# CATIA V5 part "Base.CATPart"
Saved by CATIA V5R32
Part number: Base
Bounding box of the stored display mesh (mm): x -23.876 to 23.876, y 0 to 88.9, z 0 to 54.102
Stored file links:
  D:\PROJECTS\Project 2022\CATIA V5 6R 2022\Resources\Input file\c14_catia_v5_6r2022_inp\c14_catia_v5_6r2022_inp\Base.CATPart
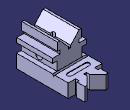
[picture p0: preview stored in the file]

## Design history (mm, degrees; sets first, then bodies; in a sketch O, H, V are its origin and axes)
Body1 (main body)
  Sketch1 on xy-plane, origin (0, 0, 0), H (1, 0, 0), V (0, 1, 0)
    line L1 (-23.876, 0) -> (23.876, 0)
    point P1 (-23.876, 0)
    point P2 (23.876, 0)
    construction line L2 (-23.876, 50.8) -> (23.876, 50.8)
    point P3 (-23.876, 50.8)
    point P4 (23.876, 50.8)
    line L3 (23.876, 0) -> (23.876, 72.898)
    point P5 (23.876, 72.898)
    line L4 (23.876, 72.898) -> (13.462, 72.898)
    point P6 (13.462, 72.898)
    line L5 (13.462, 72.898) -> (13.462, 77.724)
    point P7 (13.462, 77.724)
    line L6 (13.462, 77.724) -> (16.51, 77.724)
    point P8 (16.51, 77.724)
    line L7 (16.51, 77.724) -> (16.51, 88.9)
    point P9 (16.51, 88.9)
    line L8 (16.51, 88.9) -> (13.462, 88.9)
    point P10 (13.462, 88.9)
    line L9 (13.462, 88.9) -> (1.778, 77.724)
    point P11 (1.778, 77.724)
    line L10 (1.778, 77.724) -> (1.778, 72.898)
    point P12 (1.778, 72.898)
    line L11 (1.778, 72.898) -> (0, 72.898)
    point P13 (0, 72.898)
    point P14 (0, 72.898)
    point P15 (-1.778, 72.898)
    line L12 (-1.778, 72.898) -> (0, 72.898)
    point P16 (-1.778, 77.724)
    line L13 (-1.778, 77.724) -> (-1.778, 72.898)
    point P17 (-13.462, 88.9)
    line L14 (-13.462, 88.9) -> (-1.778, 77.724)
    point P18 (-16.51, 88.9)
    line L15 (-16.51, 88.9) -> (-13.462, 88.9)
    point P19 (-16.51, 77.724)
    line L16 (-16.51, 77.724) -> (-16.51, 88.9)
    point P20 (-13.462, 77.724)
    line L17 (-13.462, 77.724) -> (-16.51, 77.724)
    point P21 (-13.462, 72.898)
    line L18 (-13.462, 72.898) -> (-13.462, 77.724)
    point P22 (-23.876, 72.898)
    line L19 (-23.876, 72.898) -> (-13.462, 72.898)
    point P23 (-23.876, 50.8)
    point P24 (23.876, 50.8)
    construction line L20 (23.876, 50.8) -> (-23.876, 50.8)
    point P25 (-23.876, 0)
    line L21 (-23.876, 0) -> (-23.876, 72.898)
    length L1 = 47.752
    distance P2 V = 23.876
    distance L2 L1 = 50.8
    distance P5 L2 = 22.098
    distance L7 P1 = 40.386
    distance L5 P1 = 37.338
    distance L2 P7 = 26.924
    distance P9 L2 = 38.1
    distance P10 L3 = 10.414
    distance L10 L3 = 22.098
    distance L11 L2 = 22.098
    distance P11 L2 = 26.924
    horizontal: L1 H, L2 H, L4 H, L6 H, L8 H, L11 H
    coincidence: H L1, P13 V, P13 P14
    vertical: L3 V, L5 V, L7 V, L10 V
    symmetry: P13 P14 V, P12 P15 V, L11 L12 V, P11 P16 V, L10 L13 V, P10 P17 V, L9 L14 V, P9 P18 V, L8 L15 V, P8 P19 V, L7 L16 V, P7 P20 V, L6 L17 V, P6 P21 V, L5 L18 V, P5 P22 V, L4 L19 V, P4 P23 V, P3 P24 V, L2 L20 V, P2 P25 V, L3 L21 V
  Pad1: profile Sketch1, direction (0, 0, 1), length 19.05
  Sketch2 on face of Pad1, origin (23.876, 0, 0), H (0, 1, 0), V (0, 0, 1)
    point P1 (50.8, 19.05)
    line L1 (50.8, 19.05) -> (52.324, 16.4104)
    line L2 (52.324, 16.4104) -> (53.848, 19.05)
    line L3 (53.848, 19.05) -> (50.8, 19.05)
    reference projected line E1 (72.898, 19.05) -> (0, 19.05) from edge of Pad1
    length L2 = 3.048
    length L1 = 3.048
    distance P1 V = 50.8
    angle L1 L2 = 60
    horizontal: L3 H
    coincidence: L3 E1
  Pocket1: profile Sketch2, direction (-1, 0, 0), through (limit type 6)
  Sketch3 on face of Pad1, origin (0, 0, 0), H (1, 0, 0), V (0, 0, 1)
    line L1 (17.526, 19.05) -> (17.526, 31.75)
    point P1 (17.526, 19.05)
    point P2 (17.526, 31.75)
    line L2 (17.526, 31.75) -> (23.876, 31.75)
    point P3 (23.876, 31.75)
    line L3 (23.876, 31.75) -> (23.876, 38.1)
    point P4 (23.876, 38.1)
    line L4 (23.876, 38.1) -> (13.462, 38.1)
    point P5 (13.462, 38.1)
    line L5 (13.462, 38.1) -> (13.462, 42.926)
    point P6 (13.462, 42.926)
    line L6 (13.462, 42.926) -> (16.637, 42.926)
    point P7 (16.637, 42.926)
    line L7 (16.637, 42.926) -> (16.637, 54.102)
    point P8 (16.637, 54.102)
    reference projected line E1 (23.876, 19.05) -> (-23.876, 19.05) from edge of Pad1
    reference projected line E2 (23.876, 0) -> (23.876, 19.05) from edge of Pad1
    reference projected line E3 (-23.876, 19.05) -> (-23.876, 0) from edge of Pad1
    line L8 (16.637, 54.102) -> (13.462, 54.102)
    point P9 (13.462, 54.102)
    point P10 (1.651, 41.402)
    line L9 (1.651, 41.402) -> (1.651, 38.1)
    point P11 (1.651, 38.1)
    line L10 (1.651, 38.1) -> (0, 38.1)
    point P12 (0, 38.1)
    line L11 (1.651, 41.402) -> (13.462, 54.102)
    point P13 (-13.462, 54.102)
    point P14 (-1.651, 41.402)
    line L12 (-1.651, 41.402) -> (-13.462, 54.102)
    point P15 (0, 38.1)
    point P16 (-1.651, 38.1)
    line L13 (-1.651, 38.1) -> (0, 38.1)
    line L14 (-1.651, 41.402) -> (-1.651, 38.1)
    point P17 (-16.637, 54.102)
    line L15 (-16.637, 54.102) -> (-13.462, 54.102)
    point P18 (-16.637, 42.926)
    line L16 (-16.637, 42.926) -> (-16.637, 54.102)
    point P19 (-13.462, 42.926)
    line L17 (-13.462, 42.926) -> (-16.637, 42.926)
    point P20 (-13.462, 38.1)
    line L18 (-13.462, 38.1) -> (-13.462, 42.926)
    point P21 (-23.876, 38.1)
    line L19 (-23.876, 38.1) -> (-13.462, 38.1)
    point P22 (-23.876, 31.75)
    line L20 (-23.876, 31.75) -> (-23.876, 38.1)
    point P23 (-17.526, 31.75)
    line L21 (-17.526, 31.75) -> (-23.876, 31.75)
    point P24 (-17.526, 19.05)
    line L22 (-17.526, 19.05) -> (-17.526, 31.75)
    line L23 (-17.526, 19.05) -> (17.526, 19.05)
    distance V L1 = 17.526
    distance L2 H = 31.75
    distance L4 H = 38.1
    distance L6 H = 42.926
    distance L7 V = 16.637
    distance L5 E3 = 37.338
    distance V P9 = 13.462
    distance L8 H = 54.102
    distance L9 V = 1.651
    length L9 = 3.302
    vertical: L1 V, L3 V, L5 V, L7 V, L9 V
    horizontal: L2 H, L4 H, L6 H, L8 H, L10 H, L23 H
    coincidence: P1 E1, L3 E2, P11 L4, P12 V, P12 P15
    symmetry: P9 P13 V, P10 P14 V, L11 L12 V, P12 P15 V, P11 P16 V, L10 L13 V, L9 L14 V, P8 P17 V, L8 L15 V, P7 P18 V, L7 L16 V, P6 P19 V, L6 L17 V, P5 P20 V, L5 L18 V, P4 P21 V, L4 L19 V, P3 P22 V, L3 L20 V, P2 P23 V, L2 L21 V, P1 P24 V, L1 L22 V
  Pad2: profile Sketch3, direction (0, 1, 0), length 50.8
  Sketch4 on face of Pad1, origin (4.0235, 27.8102, 0), H (1, 0, 0), V (0, -1, 0)
    point P1 (-4.0235, 2.4102)
    reference projected line E1 (13.5025, -22.9898) -> (-21.5495, -22.9898) from edge of Pad2
    reference intersected line E2 through (-4.0235, 0) direction (0, 1) from yz-plane
    distance P1 E1 = 25.4
    coincidence: E2 P1
  Hole1: placed by Sketch4, at (0, 25.4, 0) direction (0, 0, 1), diameter 7.874, depth 54.102
  Sketch5 on face of Pad2, origin (17.526, 12.3932, 23.5222), H (0, 1, 0), V (0, 0, 1)
    point P1 (13.0068, 1.8778)
    reference projected line E1 (-12.3932, 8.2278) -> (-12.3932, -4.4722) from edge of Pad2
    reference projected line E2 (-12.3932, -23.5222) -> (60.5048, -23.5222) from edge of Pad1
    distance E1 P1 = 25.4
    distance E2 P1 = 25.4
  Hole2: placed by Sketch5, at (17.526, 25.4, 25.4) direction (-1, 0, 0), diameter 9.652, depth 54.102
  Sketch6 on face of Pad1, origin (0, 0, 19.05), H (1, 0, 0), V (0, 1, 0)
    construction line L1 (-23.876, 63.373) -> (23.876, 63.373)
    point P1 (-23.876, 63.373)
    point P2 (23.876, 63.373)
    reference projected line E1 (23.876, 53.848) -> (-23.876, 53.848) from edge of Pocket1
    construction line L2 (-12.7, 63.373) -> (12.7, 63.373)
    point P3 (-12.7, 63.373)
    line L3 (-12.7, 66.548) -> (12.7, 66.548)
    line L4 (12.7, 60.198) -> (-12.7, 60.198)
    arc A1 centre (12.7, 63.373) radius 3.175 from (12.7, 66.548) to (12.7, 60.198) cw
    arc A2 centre (-12.7, 63.373) radius 3.175 from (-12.7, 60.198) to (-12.7, 66.548) cw
    reference projected line E2 (23.876, 72.898) -> (23.876, 0) from edge of Pad1
    reference projected line E3 (-23.876, 72.898) -> (-23.876, 0) from edge of Pad1
    reference projected line E4 (-23.876, 72.898) -> (-23.876, 0) from edge of Pad1
    distance E1 L1 = 9.525
    radius A1 = 3.175
    distance A1 A2 = 31.75
    distance P3 E4 = 11.176
    horizontal: L1 H, L2 H
    coincidence: P3 L1, P2 E2, P1 E3
    tangency: A1 L3, A2 L3, A1 L4, A2 L4
    parallelism: L2 L3
  Pocket2: profile Sketch6, direction (0, 0, -1), length 0.762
